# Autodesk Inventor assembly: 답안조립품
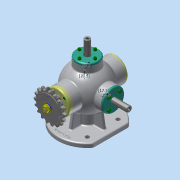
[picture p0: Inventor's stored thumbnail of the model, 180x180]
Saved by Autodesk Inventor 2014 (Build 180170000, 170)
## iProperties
Created: 2016-03
Part Number: 답안조립품
Document SubType Name: Assembly
Designer: SCD-A13
Mass: 3000.8 g
Surface Area: 2215.45 cm^2
Volume: 826.204 cm^3
Density: 3.63203 g/cm^3
Author: SCD-A13
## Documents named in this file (17)
- C:\Users\SCD-A13\Desktop\360307V1023\답안조립품.iam
- C:\Users\SCD-A13\Desktop\360307V1023\너트-M8x1.ipt
- C:\Users\SCD-A13\Desktop\360307V1023\뒤커버.ipt
- C:\Users\SCD-A13\Desktop\360307V1023\베어링- 6202.ipt
- C:\Users\SCD-A13\Desktop\360307V1023\본체.ipt
- C:\Users\SCD-A13\Desktop\360307V1023\본체커버.ipt
- C:\Users\SCD-A13\Desktop\360307V1023\볼트 M4x0.7.ipt
- C:\Users\SCD-A13\Desktop\360307V1023\스프로킷.ipt
- C:\Users\SCD-A13\Desktop\360307V1023\스프링_15.ipt
- C:\Users\SCD-A13\Desktop\360307V1023\스프링_16.ipt
- C:\Users\SCD-A13\Desktop\360307V1023\슬라이드 커버.ipt
- C:\Users\SCD-A13\Desktop\360307V1023\슬라이드.ipt
- C:\Users\SCD-A13\Desktop\360307V1023\앞커버.ipt
- C:\Users\SCD-A13\Desktop\360307V1023\오일실.ipt
- C:\Users\SCD-A13\Desktop\360307V1023\와셔 8x17.ipt
- C:\Users\SCD-A13\Desktop\360307V1023\축.ipt
- C:\Users\SCD-A13\Desktop\360307V1023\키 3 x 3 x 12.ipt
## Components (17 placed, 1 different names)
1. M4x0.7x12:17
2. M4x0.7x12:2
3. M4x0.7x12:3
4. M4x0.7x12:4
5. M4x0.7x12:5
6. M4x0.7x12:1
7. M4x0.7x12:6
8. M4x0.7x12:7
9. M4x0.7x12:8
10. M4x0.7x12:10
11. M4x0.7x12:11
12. M4x0.7x12:12
13. M4x0.7x12:13
14. M4x0.7x12:9
15. M4x0.7x12:14
16. M4x0.7x12:15
17. M4x0.7x12:16
